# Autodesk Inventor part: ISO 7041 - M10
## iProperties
Created: 2001-08
Part Number: ISO 7041 - M10
Catalog Web Link: file:///D:/Program%20Files/Autodesk/Inventor%205/Content/Iso/index.htm?doNavigateId=91C8CC99-3893-4F49-8D02-DF1401D4CEFB|57F98C91C2674527A08DA124A942906D|true
Description: Hex Nut with Torque Part
Document SubType Name: Standard Catalog Part
Standard: ISO 7041 - M10
Designer: Martin Budgell
Control State: 0
Master: False
Checked Out: False
Length Units: 11269
Angle Units: 11279
Time Units: 11290
Mass Units: 11283
Shininess: 3
Angle Display Precision: 2
Document Length Units: 11269
Document Angle Units: 11279
Document Time Units: 11290
Document Mass Units: 11283
Document Length Units Precision: 3
Document Angle Units Precision: 2
Compacted: True
CLASSIFICATION: 31161727 un/spsc
MANUFACTURER: ISO Standard System
Density: 0.0
Volumn: 0.0
Area: 0.0
PropertySet Name: Model Information
Author: Martin Budgell
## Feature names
1. Base1
